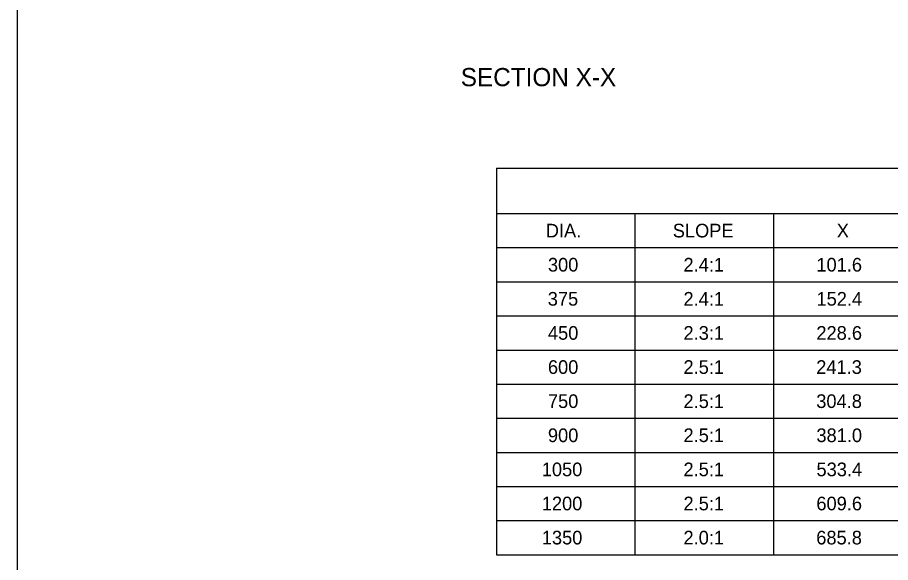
# Model space of a CAD drawing. Extents: x 49991.4 to 50022.1, y 49985 to 50011.4.
# Drawn here: x 49999.384 to 50003.224, y 49992.942 to 49995.339 of the extents above; entities that cross this region are included whole.
import ezdxf

# ---------------------------------------------------------------- set-up
doc = ezdxf.new("R2010")
doc.units = 0
doc.layers.add('Level 1', color=7, linetype='Continuous')
doc.layers.add('Level 2', color=7, linetype='Continuous')

msp = doc.modelspace()

# ---------------------------------------------------------------- linework, layer by layer
at = {"layer": 'Level 1'}
msp.add_lwpolyline([(49999.3835, 49998.9992), (50016.7501, 49998.9992), (50016.7501, 49987.7988), (49999.3835, 49987.7988)], close=True, dxfattribs=at)
at = {"layer": 'Level 2'}
for p, q in [((50001.4902, 49994.677), (50001.4902, 49992.977)), ((50001.4902, 49994.677), (50006.3702, 49994.677)), ((50001.4902, 49994.477), (50006.3702, 49994.477)), ((50002.1002, 49994.477), (50002.1002, 49992.977)), ((50002.7102, 49994.477), (50002.7102, 49992.977)), ((50001.4902, 49994.327), (50006.3702, 49994.327)), ((50001.4902, 49994.177), (50006.3702, 49994.177)), ((50001.4902, 49994.027), (50006.3702, 49994.027)), ((50001.4902, 49993.877), (50006.3702, 49993.877)), ((50001.4902, 49993.727), (50006.3702, 49993.727)), ((50001.4902, 49993.577), (50006.3702, 49993.577)), ((50001.4902, 49993.427), (50006.3702, 49993.427)), ((50001.4902, 49993.277), (50006.3702, 49993.277)), ((50001.4902, 49993.127), (50006.3702, 49993.127)), ((50001.4902, 49992.977), (50006.3702, 49992.977))]:
    msp.add_line(p, q, dxfattribs=at)

# ---------------------------------------------------------------- texts
for s, height, p in [('SECTION X-X', 0.08, (50001.3337, 49995.037)), ('DIA.', 0.06, (50001.7077, 49994.372)), ('SLOPE', 0.06, (50002.2664, 49994.372)), ('X', 0.06, (50002.9878, 49994.372)), ('300', 0.06, (50001.7171, 49994.222)), ('2.4:1', 0.06, (50002.3135, 49994.222)), ('101.6', 0.06, (50002.8981, 49994.222)), ('375', 0.06, (50001.7164, 49994.072)), ('2.4:1', 0.06, (50002.3135, 49994.072)), ('152.4', 0.06, (50002.8986, 49994.072)), ('450', 0.06, (50001.7171, 49993.922)), ('2.3:1', 0.06, (50002.3135, 49993.922)), ('228.6', 0.06, (50002.8981, 49993.922)), ('600', 0.06, (50001.7171, 49993.772)), ('2.5:1', 0.06, (50002.3135, 49993.772)), ('241.3', 0.06, (50002.8974, 49993.772)), ('750', 0.06, (50001.7171, 49993.622)), ('2.5:1', 0.06, (50002.3135, 49993.622)), ('304.8', 0.06, (50002.8976, 49993.622)), ('900', 0.06, (50001.7171, 49993.472)), ('2.5:1', 0.06, (50002.3135, 49993.472)), ('381.0', 0.06, (50002.8983, 49993.472)), ('1050', 0.06, (50001.6901, 49993.322)), ('2.5:1', 0.06, (50002.3135, 49993.322)), ('533.4', 0.06, (50002.8986, 49993.322)), ('1200', 0.06, (50001.6901, 49993.172)), ('2.5:1', 0.06, (50002.3135, 49993.172)), ('609.6', 0.06, (50002.8981, 49993.172)), ('1350', 0.06, (50001.6901, 49993.022)), ('2.0:1', 0.06, (50002.3135, 49993.022)), ('685.8', 0.06, (50002.8976, 49993.022))]:
    msp.add_text(s, height=height, dxfattribs=at).set_placement(p)

doc.saveas('drawing.dxf')
